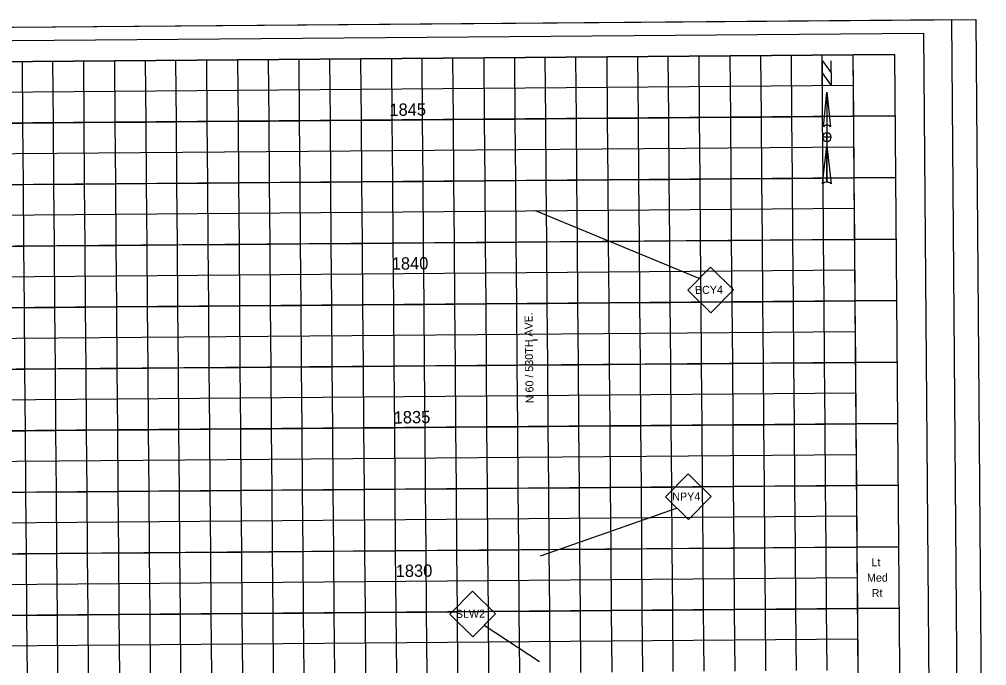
# Model space of a CAD drawing. Extents: x 11670159 to 11702568, y 9558247 to 9571922.
# Drawn here: x 11687520 to 11690664, y 9568756 to 9570857 of the extents above; entities that cross this region are included whole.
import ezdxf

# ---------------------------------------------------------------- set-up
doc = ezdxf.new("R2010")
doc.units = 0
for name, color, linetype in [('dsnAlignmentStation', 7, 'Continuous'), ('dsnNonPlotable', 7, 'Continuous'), ('DsnShtDBGLtRtTextUpper', 7, 'Continuous'), ('DsnShtDBGMedTextUpper', 7, 'Continuous'), ('DsnShtMajorGrid11', 7, 'Continuous'), ('DsnShtMajorGrid12', 7, 'Continuous'), ('DsnShtMajorGrid13', 7, 'Continuous'), ('DsnShtMajorGrid14', 7, 'Continuous'), ('DsnShtMajorGrid15', 7, 'Continuous'), ('DsnShtMajorGrid16', 7, 'Continuous'), ('DsnShtMajorGrid17', 7, 'Continuous'), ('DsnShtMajorGrid18', 7, 'Continuous'), ('DsnShtMajorGrid19', 7, 'Continuous'), ('DsnShtMajorGrid20', 7, 'Continuous'), ('DsnShtMinorGrid11', 7, 'Continuous'), ('DsnShtMinorGrid12', 7, 'Continuous'), ('DsnShtMinorGrid13', 7, 'Continuous'), ('DsnShtMinorGrid14', 7, 'Continuous'), ('DsnShtMinorGrid15', 7, 'Continuous'), ('DsnShtMinorGrid16', 7, 'Continuous'), ('DsnShtMinorGrid17', 7, 'Continuous'), ('DsnShtMinorGrid18', 7, 'Continuous'), ('DsnShtMinorGrid19', 7, 'Continuous'), ('DsnShtMinorGrid20', 7, 'Continuous'), ('DsnShtOutsideBorder', 7, 'Continuous'), ('DsnShtPlotShape', 7, 'Continuous'), ('dsnShtPlotShapeBatchPrint', 7, 'Continuous'), ('dsnTextFinalPlan', 7, 'Continuous'), ('hwyPlanSheetShape', 7, 'Continuous'), ('PvmtMrkngPrplCallout', 7, 'Continuous')]:
    doc.layers.add(name, color=color, linetype=linetype)

msp = doc.modelspace()

# ---------------------------------------------------------------- linework, layer by layer
at = {"layer": 'dsnNonPlotable'}
msp.add_line((11689189, 9569814.8), (11689203.6, 9569815), dxfattribs=at)
msp.add_lwpolyline([(11684229.4, 9570693), (11690229.2, 9570741.4), (11690261.8, 9566701.6), (11684262, 9566653.2)], close=True, dxfattribs=at)
at = {"layer": 'DsnShtMajorGrid11'}
for points in [[(11690378.7, 9568942.6), (11684108.9, 9568892)], [(11687645.4, 9568720.5), (11687643.8, 9568920.5), (11687843.8, 9568922.1), (11687845.4, 9568722.1)], [(11688045.4, 9568723.7), (11688043.8, 9568923.7), (11688243.8, 9568925.3), (11688245.4, 9568725.4)], [(11688445.4, 9568727), (11688443.8, 9568927), (11688643.8, 9568928.6), (11688645.4, 9568728.6)], [(11688845.4, 9568730.2), (11688843.8, 9568930.2), (11689043.7, 9568931.8), (11689045.4, 9568731.8)], [(11689245.4, 9568733.4), (11689243.7, 9568933.4), (11689443.7, 9568935), (11689445.3, 9568735)], [(11689645.3, 9568736.6), (11689643.7, 9568936.6), (11689843.7, 9568938.3), (11689845.3, 9568738.3)], [(11690045.3, 9568739.9), (11690043.7, 9568939.9), (11690243.7, 9568941.5), (11690245.3, 9568741.5)]]:
    msp.add_lwpolyline(points, dxfattribs=at)
at = {"layer": 'DsnShtMajorGrid12'}
for points in [[(11690377.1, 9569142.6), (11684107.3, 9569092)], [(11687443.8, 9568918.9), (11687643.8, 9568920.5), (11687642.2, 9569120.5), (11687842.2, 9569122.1), (11687843.8, 9568922.1), (11688043.8, 9568923.7), (11688042.2, 9569123.7), (11688242.2, 9569125.3), (11688243.8, 9568925.3), (11688443.8, 9568927), (11688442.2, 9569127), (11688642.1, 9569128.6), (11688643.8, 9568928.6), (11688843.8, 9568930.2), (11688842.1, 9569130.2), (11689042.1, 9569131.8), (11689043.7, 9568931.8), (11689243.7, 9568933.4), (11689242.1, 9569133.4), (11689442.1, 9569135), (11689443.7, 9568935), (11689643.7, 9568936.6), (11689642.1, 9569136.6), (11689842.1, 9569138.2), (11689843.7, 9568938.3), (11690043.7, 9568939.9), (11690042.1, 9569139.9), (11690242.1, 9569141.5), (11690243.7, 9568941.5), (11690378.7, 9568942.6), (11684108.9, 9568892)]]:
    msp.add_lwpolyline(points, dxfattribs=at)
at = {"layer": 'DsnShtMajorGrid13'}
for points in [[(11690375.5, 9569342.6), (11684105.7, 9569292)], [(11687442.2, 9569118.9), (11687642.2, 9569120.5), (11687640.6, 9569320.5), (11687840.6, 9569322.1), (11687842.2, 9569122.1), (11688042.2, 9569123.7), (11688040.6, 9569323.7), (11688240.5, 9569325.3), (11688242.2, 9569125.3), (11688442.2, 9569127), (11688440.5, 9569326.9), (11688640.5, 9569328.6), (11688642.1, 9569128.6), (11688842.1, 9569130.2), (11688840.5, 9569330.2), (11689040.5, 9569331.8), (11689042.1, 9569131.8), (11689242.1, 9569133.4), (11689240.5, 9569333.4), (11689440.5, 9569335), (11689442.1, 9569135), (11689642.1, 9569136.6), (11689640.5, 9569336.6), (11689840.5, 9569338.2), (11689842.1, 9569138.2), (11690042.1, 9569139.9), (11690040.5, 9569339.9), (11690240.5, 9569341.5), (11690242.1, 9569141.5), (11690377.1, 9569142.6), (11684107.3, 9569092)]]:
    msp.add_lwpolyline(points, dxfattribs=at)
at = {"layer": 'DsnShtMajorGrid14'}
for points in [[(11690373.9, 9569542.5), (11684104.1, 9569492)], [(11687440.6, 9569318.9), (11687640.6, 9569320.5), (11687639, 9569520.5), (11687838.9, 9569522.1), (11687840.6, 9569322.1), (11688040.6, 9569323.7), (11688038.9, 9569523.7), (11688238.9, 9569525.3), (11688240.5, 9569325.3), (11688440.5, 9569326.9), (11688438.9, 9569526.9), (11688638.9, 9569528.6), (11688640.5, 9569328.6), (11688840.5, 9569330.2), (11688838.9, 9569530.2), (11689038.9, 9569531.8), (11689040.5, 9569331.8), (11689240.5, 9569333.4), (11689238.9, 9569533.4), (11689438.9, 9569535), (11689440.5, 9569335), (11689640.5, 9569336.6), (11689638.9, 9569536.6), (11689838.9, 9569538.2), (11689840.5, 9569338.2), (11690040.5, 9569339.9), (11690038.9, 9569539.8), (11690238.9, 9569541.5), (11690240.5, 9569341.5), (11690375.5, 9569342.6), (11684105.7, 9569292)]]:
    msp.add_lwpolyline(points, dxfattribs=at)
at = {"layer": 'DsnShtMajorGrid15'}
for points in [[(11690372.3, 9569742.5), (11684102.5, 9569692)], [(11687439, 9569518.9), (11687639, 9569520.5), (11687637.3, 9569720.5), (11687837.3, 9569722.1), (11687838.9, 9569522.1), (11688038.9, 9569523.7), (11688037.3, 9569723.7), (11688237.3, 9569725.3), (11688238.9, 9569525.3), (11688438.9, 9569526.9), (11688437.3, 9569726.9), (11688637.3, 9569728.5), (11688638.9, 9569528.6), (11688838.9, 9569530.2), (11688837.3, 9569730.2), (11689037.3, 9569731.8), (11689038.9, 9569531.8), (11689238.9, 9569533.4), (11689237.3, 9569733.4), (11689437.3, 9569735), (11689438.9, 9569535), (11689638.9, 9569536.6), (11689637.3, 9569736.6), (11689837.3, 9569738.2), (11689838.9, 9569538.2), (11690038.9, 9569539.8), (11690037.3, 9569739.8), (11690237.3, 9569741.5), (11690238.9, 9569541.5), (11690373.9, 9569542.5), (11684104.1, 9569492)]]:
    msp.add_lwpolyline(points, dxfattribs=at)
at = {"layer": 'DsnShtMajorGrid16'}
for points in [[(11690370.6, 9569942.5), (11684100.8, 9569892)], [(11687437.3, 9569718.9), (11687637.3, 9569720.5), (11687635.7, 9569920.5), (11687835.7, 9569922.1), (11687837.3, 9569722.1), (11688037.3, 9569723.7), (11688035.7, 9569923.7), (11688235.7, 9569925.3), (11688237.3, 9569725.3), (11688437.3, 9569726.9), (11688435.7, 9569926.9), (11688635.7, 9569928.5), (11688637.3, 9569728.5), (11688837.3, 9569730.2), (11688835.7, 9569930.2), (11689035.7, 9569931.8), (11689037.3, 9569731.8), (11689237.3, 9569733.4), (11689235.7, 9569933.4), (11689435.7, 9569935), (11689437.3, 9569735), (11689637.3, 9569736.6), (11689635.7, 9569936.6), (11689835.7, 9569938.2), (11689837.3, 9569738.2), (11690037.3, 9569739.8), (11690035.7, 9569939.8), (11690235.6, 9569941.4), (11690237.3, 9569741.5), (11690372.3, 9569742.5), (11684102.5, 9569692)]]:
    msp.add_lwpolyline(points, dxfattribs=at)
at = {"layer": 'DsnShtMajorGrid17'}
for points in [[(11690369, 9570142.5), (11684099.2, 9570092)], [(11687435.7, 9569918.9), (11687635.7, 9569920.5), (11687634.1, 9570120.5), (11687834.1, 9570122.1), (11687835.7, 9569922.1), (11688035.7, 9569923.7), (11688034.1, 9570123.7), (11688234.1, 9570125.3), (11688235.7, 9569925.3), (11688435.7, 9569926.9), (11688434.1, 9570126.9), (11688634.1, 9570128.5), (11688635.7, 9569928.5), (11688835.7, 9569930.2), (11688834.1, 9570130.1), (11689034.1, 9570131.8), (11689035.7, 9569931.8), (11689235.7, 9569933.4), (11689234.1, 9570133.4), (11689434.1, 9570135), (11689435.7, 9569935), (11689635.7, 9569936.6), (11689634.1, 9570136.6), (11689834, 9570138.2), (11689835.7, 9569938.2), (11690035.7, 9569939.8), (11690034, 9570139.8), (11690234, 9570141.4), (11690235.6, 9569941.4), (11690370.6, 9569942.5), (11684100.8, 9569892)]]:
    msp.add_lwpolyline(points, dxfattribs=at)
at = {"layer": 'DsnShtMajorGrid18'}
for points in [[(11690367.4, 9570342.5), (11684097.6, 9570291.9)], [(11687434.1, 9570118.9), (11687634.1, 9570120.5), (11687632.5, 9570320.5), (11687832.5, 9570322.1), (11687834.1, 9570122.1), (11688034.1, 9570123.7), (11688032.5, 9570323.7), (11688232.5, 9570325.3), (11688234.1, 9570125.3), (11688434.1, 9570126.9), (11688432.5, 9570326.9), (11688632.5, 9570328.5), (11688634.1, 9570128.5), (11688834.1, 9570130.1), (11688832.5, 9570330.1), (11689032.5, 9570331.8), (11689034.1, 9570131.8), (11689234.1, 9570133.4), (11689232.5, 9570333.4), (11689432.4, 9570335), (11689434.1, 9570135), (11689634.1, 9570136.6), (11689632.4, 9570336.6), (11689832.4, 9570338.2), (11689834, 9570138.2), (11690034, 9570139.8), (11690032.4, 9570339.8), (11690232.4, 9570341.4), (11690234, 9570141.4), (11690369, 9570142.5), (11684099.2, 9570092)]]:
    msp.add_lwpolyline(points, dxfattribs=at)
at = {"layer": 'DsnShtMajorGrid19'}
for points in [[(11690365.8, 9570542.5), (11684096, 9570491.9)], [(11687432.5, 9570318.8), (11687632.5, 9570320.5), (11687630.9, 9570520.5), (11687830.9, 9570522.1), (11687832.5, 9570322.1), (11688032.5, 9570323.7), (11688030.9, 9570523.7), (11688230.9, 9570525.3), (11688232.5, 9570325.3), (11688432.5, 9570326.9), (11688430.9, 9570526.9), (11688630.9, 9570528.5), (11688632.5, 9570328.5), (11688832.5, 9570330.1), (11688830.8, 9570530.1), (11689030.8, 9570531.7), (11689032.5, 9570331.8), (11689232.5, 9570333.4), (11689230.8, 9570533.4), (11689430.8, 9570535), (11689432.4, 9570335), (11689632.4, 9570336.6), (11689630.8, 9570536.6), (11689830.8, 9570538.2), (11689832.4, 9570338.2), (11690032.4, 9570339.8), (11690030.8, 9570539.8), (11690230.8, 9570541.4), (11690232.4, 9570341.4), (11690367.4, 9570342.5), (11684097.6, 9570291.9)]]:
    msp.add_lwpolyline(points, dxfattribs=at)
at = {"layer": 'DsnShtMajorGrid20'}
for points in [[(11690364.2, 9570742.5), (11684094.4, 9570691.9)], [(11687430.9, 9570518.8), (11687630.9, 9570520.5), (11687629.3, 9570720.4), (11687829.3, 9570722.1), (11687830.9, 9570522.1), (11688030.9, 9570523.7), (11688029.3, 9570723.7), (11688229.3, 9570725.3), (11688230.9, 9570525.3), (11688430.9, 9570526.9), (11688429.2, 9570726.9), (11688629.2, 9570728.5), (11688630.9, 9570528.5), (11688830.8, 9570530.1), (11688829.2, 9570730.1), (11689029.2, 9570731.7), (11689030.8, 9570531.7), (11689230.8, 9570533.4), (11689229.2, 9570733.4), (11689429.2, 9570735), (11689430.8, 9570535), (11689630.8, 9570536.6), (11689629.2, 9570736.6), (11689829.2, 9570738.2), (11689830.8, 9570538.2), (11690030.8, 9570539.8), (11690029.2, 9570739.8), (11690229.2, 9570741.4), (11690230.8, 9570541.4), (11690365.8, 9570542.5), (11684096, 9570491.9)]]:
    msp.add_lwpolyline(points, dxfattribs=at)
at = {"layer": 'DsnShtMinorGrid11'}
for points in [[(11687343.8, 9568918.1), (11687543.8, 9568919.7), (11687545.4, 9568719.7)], [(11687745.4, 9568721.3), (11687743.8, 9568921.3), (11687943.8, 9568922.9), (11687945.4, 9568722.9)], [(11688145.4, 9568724.5), (11688143.8, 9568924.5), (11688343.8, 9568926.2), (11688345.4, 9568726.2)], [(11688545.4, 9568727.8), (11688543.8, 9568927.8), (11688743.8, 9568929.4), (11688745.4, 9568729.4)], [(11688945.4, 9568731), (11688943.8, 9568931), (11689143.7, 9568932.6), (11689145.4, 9568732.6)], [(11689345.4, 9568734.2), (11689343.7, 9568934.2), (11689543.7, 9568935.8), (11689545.3, 9568735.8)], [(11689745.3, 9568737.5), (11689743.7, 9568937.4), (11689943.7, 9568939.1), (11689945.3, 9568739.1)], [(11690145.3, 9568740.7), (11690143.7, 9568940.7)], [(11690244.5, 9568841.5), (11684244.7, 9568793.1)]]:
    msp.add_lwpolyline(points, dxfattribs=at)
at = {"layer": 'DsnShtMinorGrid12'}
for points in [[(11687342.2, 9569118.1), (11687542.2, 9569119.7), (11687543.8, 9568919.7), (11687743.8, 9568921.3), (11687742.2, 9569121.3), (11687942.2, 9569122.9), (11687943.8, 9568922.9), (11688143.8, 9568924.5), (11688142.2, 9569124.5), (11688342.2, 9569126.1), (11688343.8, 9568926.2), (11688543.8, 9568927.8), (11688542.2, 9569127.8), (11688742.1, 9569129.4), (11688743.8, 9568929.4), (11688943.8, 9568931), (11688942.1, 9569131), (11689142.1, 9569132.6), (11689143.7, 9568932.6), (11689343.7, 9568934.2), (11689342.1, 9569134.2), (11689542.1, 9569135.8), (11689543.7, 9568935.8), (11689743.7, 9568937.4), (11689742.1, 9569137.4), (11689942.1, 9569139.1), (11689943.7, 9568939.1), (11690143.7, 9568940.7), (11690142.1, 9569140.7)], [(11690242.9, 9569041.5), (11684243.1, 9568993.1)]]:
    msp.add_lwpolyline(points, dxfattribs=at)
at = {"layer": 'DsnShtMinorGrid13'}
for points in [[(11687340.6, 9569318.1), (11687540.6, 9569319.7), (11687542.2, 9569119.7), (11687742.2, 9569121.3), (11687740.6, 9569321.3), (11687940.6, 9569322.9), (11687942.2, 9569122.9), (11688142.2, 9569124.5), (11688140.6, 9569324.5), (11688340.5, 9569326.1), (11688342.2, 9569126.1), (11688542.2, 9569127.8), (11688540.5, 9569327.8), (11688740.5, 9569329.4), (11688742.1, 9569129.4), (11688942.1, 9569131), (11688940.5, 9569331), (11689140.5, 9569332.6), (11689142.1, 9569132.6), (11689342.1, 9569134.2), (11689340.5, 9569334.2), (11689540.5, 9569335.8), (11689542.1, 9569135.8), (11689742.1, 9569137.4), (11689740.5, 9569337.4), (11689940.5, 9569339), (11689942.1, 9569139.1), (11690142.1, 9569140.7), (11690140.5, 9569340.7)], [(11690241.3, 9569241.5), (11684241.5, 9569193.1)]]:
    msp.add_lwpolyline(points, dxfattribs=at)
at = {"layer": 'DsnShtMinorGrid14'}
for points in [[(11687339, 9569518.1), (11687539, 9569519.7), (11687540.6, 9569319.7), (11687740.6, 9569321.3), (11687739, 9569521.3), (11687938.9, 9569522.9), (11687940.6, 9569322.9), (11688140.6, 9569324.5), (11688138.9, 9569524.5), (11688338.9, 9569526.1), (11688340.5, 9569326.1), (11688540.5, 9569327.8), (11688538.9, 9569527.7), (11688738.9, 9569529.4), (11688740.5, 9569329.4), (11688940.5, 9569331), (11688938.9, 9569531), (11689138.9, 9569532.6), (11689140.5, 9569332.6), (11689340.5, 9569334.2), (11689338.9, 9569534.2), (11689538.9, 9569535.8), (11689540.5, 9569335.8), (11689740.5, 9569337.4), (11689738.9, 9569537.4), (11689938.9, 9569539), (11689940.5, 9569339), (11690140.5, 9569340.7), (11690138.9, 9569540.7)], [(11690239.7, 9569441.5), (11684239.9, 9569393.1)]]:
    msp.add_lwpolyline(points, dxfattribs=at)
at = {"layer": 'DsnShtMinorGrid15'}
for points in [[(11687337.4, 9569718.1), (11687537.3, 9569719.7), (11687539, 9569519.7), (11687739, 9569521.3), (11687737.3, 9569721.3), (11687937.3, 9569722.9), (11687938.9, 9569522.9), (11688138.9, 9569524.5), (11688137.3, 9569724.5), (11688337.3, 9569726.1), (11688338.9, 9569526.1), (11688538.9, 9569527.7), (11688537.3, 9569727.7), (11688737.3, 9569729.4), (11688738.9, 9569529.4), (11688938.9, 9569531), (11688937.3, 9569731), (11689137.3, 9569732.6), (11689138.9, 9569532.6), (11689338.9, 9569534.2), (11689337.3, 9569734.2), (11689537.3, 9569735.8), (11689538.9, 9569535.8), (11689738.9, 9569537.4), (11689737.3, 9569737.4), (11689937.3, 9569739), (11689938.9, 9569539), (11690138.9, 9569540.7), (11690137.3, 9569740.6)], [(11690238.1, 9569641.5), (11684238.3, 9569593.1)]]:
    msp.add_lwpolyline(points, dxfattribs=at)
at = {"layer": 'DsnShtMinorGrid16'}
for points in [[(11687335.7, 9569918.1), (11687535.7, 9569919.7), (11687537.3, 9569719.7), (11687737.3, 9569721.3), (11687735.7, 9569921.3), (11687935.7, 9569922.9), (11687937.3, 9569722.9), (11688137.3, 9569724.5), (11688135.7, 9569924.5), (11688335.7, 9569926.1), (11688337.3, 9569726.1), (11688537.3, 9569727.7), (11688535.7, 9569927.7), (11688735.7, 9569929.3), (11688737.3, 9569729.4), (11688937.3, 9569731), (11688935.7, 9569931), (11689135.7, 9569932.6), (11689137.3, 9569732.6), (11689337.3, 9569734.2), (11689335.7, 9569934.2), (11689535.7, 9569935.8), (11689537.3, 9569735.8), (11689737.3, 9569737.4), (11689735.7, 9569937.4), (11689935.7, 9569939), (11689937.3, 9569739), (11690137.3, 9569740.6), (11690135.6, 9569940.6)], [(11690236.5, 9569841.4), (11684236.6, 9569793.1)]]:
    msp.add_lwpolyline(points, dxfattribs=at)
at = {"layer": 'DsnShtMinorGrid17'}
for points in [[(11687334.1, 9570118), (11687534.1, 9570119.7), (11687535.7, 9569919.7), (11687735.7, 9569921.3), (11687734.1, 9570121.3), (11687934.1, 9570122.9), (11687935.7, 9569922.9), (11688135.7, 9569924.5), (11688134.1, 9570124.5), (11688334.1, 9570126.1), (11688335.7, 9569926.1), (11688535.7, 9569927.7), (11688534.1, 9570127.7), (11688734.1, 9570129.3), (11688735.7, 9569929.3), (11688935.7, 9569931), (11688934.1, 9570131), (11689134.1, 9570132.6), (11689135.7, 9569932.6), (11689335.7, 9569934.2), (11689334.1, 9570134.2), (11689534.1, 9570135.8), (11689535.7, 9569935.8), (11689735.7, 9569937.4), (11689734, 9570137.4), (11689934, 9570139), (11689935.7, 9569939), (11690135.6, 9569940.6), (11690134, 9570140.6)], [(11690234.8, 9570041.4), (11684235, 9569993)]]:
    msp.add_lwpolyline(points, dxfattribs=at)
at = {"layer": 'DsnShtMinorGrid18'}
for points in [[(11687332.5, 9570318), (11687532.5, 9570319.7), (11687534.1, 9570119.7), (11687734.1, 9570121.3), (11687732.5, 9570321.3), (11687932.5, 9570322.9), (11687934.1, 9570122.9), (11688134.1, 9570124.5), (11688132.5, 9570324.5), (11688332.5, 9570326.1), (11688334.1, 9570126.1), (11688534.1, 9570127.7), (11688532.5, 9570327.7), (11688732.5, 9570329.3), (11688734.1, 9570129.3), (11688934.1, 9570131), (11688932.5, 9570330.9), (11689132.5, 9570332.6), (11689134.1, 9570132.6), (11689334.1, 9570134.2), (11689332.4, 9570334.2), (11689532.4, 9570335.8), (11689534.1, 9570135.8), (11689734, 9570137.4), (11689732.4, 9570337.4), (11689932.4, 9570339), (11689934, 9570139), (11690134, 9570140.6), (11690132.4, 9570340.6)], [(11690233.2, 9570241.4), (11684233.4, 9570193)]]:
    msp.add_lwpolyline(points, dxfattribs=at)
at = {"layer": 'DsnShtMinorGrid19'}
for points in [[(11687330.9, 9570518), (11687530.9, 9570519.6), (11687532.5, 9570319.7), (11687732.5, 9570321.3), (11687730.9, 9570521.3), (11687930.9, 9570522.9), (11687932.5, 9570322.9), (11688132.5, 9570324.5), (11688130.9, 9570524.5), (11688330.9, 9570526.1), (11688332.5, 9570326.1), (11688532.5, 9570327.7), (11688530.9, 9570527.7), (11688730.9, 9570529.3), (11688732.5, 9570329.3), (11688932.5, 9570330.9), (11688930.8, 9570530.9), (11689130.8, 9570532.6), (11689132.5, 9570332.6), (11689332.4, 9570334.2), (11689330.8, 9570534.2), (11689530.8, 9570535.8), (11689532.4, 9570335.8), (11689732.4, 9570337.4), (11689730.8, 9570537.4), (11689930.8, 9570539), (11689932.4, 9570339), (11690132.4, 9570340.6), (11690130.8, 9570540.6)], [(11690231.6, 9570441.4), (11684231.8, 9570393)]]:
    msp.add_lwpolyline(points, dxfattribs=at)
at = {"layer": 'DsnShtMinorGrid20'}
for points in [[(11687329.3, 9570718), (11687529.3, 9570719.6), (11687530.9, 9570519.6), (11687730.9, 9570521.3), (11687729.3, 9570721.3), (11687929.3, 9570722.9), (11687930.9, 9570522.9), (11688130.9, 9570524.5), (11688129.3, 9570724.5), (11688329.3, 9570726.1), (11688330.9, 9570526.1), (11688530.9, 9570527.7), (11688529.2, 9570727.7), (11688729.2, 9570729.3), (11688730.9, 9570529.3), (11688930.8, 9570530.9), (11688929.2, 9570730.9), (11689129.2, 9570732.5), (11689130.8, 9570532.6), (11689330.8, 9570534.2), (11689329.2, 9570734.2), (11689529.2, 9570735.8), (11689530.8, 9570535.8), (11689730.8, 9570537.4), (11689729.2, 9570737.4), (11689929.2, 9570739), (11689930.8, 9570539), (11690130.8, 9570540.6), (11690129.2, 9570740.6)], [(11690230, 9570641.4), (11684230.2, 9570593)]]:
    msp.add_lwpolyline(points, dxfattribs=at)
at = {"layer": 'DsnShtOutsideBorder'}
msp.add_lwpolyline([(11684094.4, 9570691.9), (11690364.2, 9570742.5), (11690397.4, 9566622.6), (11684127.6, 9566572.1)], close=True, dxfattribs=at)
at = {"layer": 'DsnShtPlotShape'}
msp.add_lwpolyline([(11683828.5, 9570801.8), (11690628.3, 9570856.6), (11690663.8, 9566456.8), (11683864, 9566401.9)], close=True, dxfattribs=at)
at = {"layer": 'dsnShtPlotShapeBatchPrint'}
msp.add_lwpolyline([(11683907.6, 9570802.4), (11690549.2, 9570856), (11690584.6, 9566469.3), (11683943, 9566415.7)], close=True, dxfattribs=at)
at = {"layer": 'dsnTextFinalPlan'}
for p, q in [((11690144.8, 9570620.4), (11690156.1, 9570507.8)), ((11690144.8, 9570620.4), (11690144.8, 9570327.5)), ((11690133.6, 9570507.8), (11690133.6, 9570507.8)), ((11690134, 9570508.8), (11690136.1, 9570511.2)), ((11690144.8, 9570459.9), (11690144.8, 9570459.9)), ((11690130.7, 9570321.9), (11690144.8, 9570445.8))]:
    msp.add_line(p, q, dxfattribs=at)
for points in [[(11690130.7, 9570643), (11690130.8, 9570721.8), (11690158.9, 9570682.4), (11690158.9, 9570721.8)], [(11690133.6, 9570507.8), (11690144.8, 9570620.4), (11690144.8, 9570513.4)], [(11690144.8, 9570459.9), (11690144.8, 9570474), (11690130.7, 9570474)], [(11690158.9, 9570474), (11690144.8, 9570474), (11690144.8, 9570488.1)], [(11690144.8, 9570327.5), (11690144.8, 9570445.8), (11690158.9, 9570321.9)]]:
    msp.add_lwpolyline(points, dxfattribs=at)
msp.add_lwpolyline([(11690158.9, 9570643), (11690130.8, 9570682.4), (11690130.8, 9570721.8), (11690158.9, 9570682.4)], close=True, dxfattribs=at)
for centre, radius, start, end in [((11690144.8, 9570499.3), 14.1, 90.0161, 143.1215), ((11690144.8, 9570499.3), 14.1, 36.8438, 90.0176), ((11690144.8, 9570474), 14.1, 89.9957, 179.9957), ((11690144.8, 9570474), 14.1, 179.9957, 269.9957), ((11690144.8, 9570474), 14.1, 359.9957, 89.9957), ((11690144.8, 9570474), 14.1, 269.9957, 359.9957), ((11690144.8, 9570307.1), 20.4, 89.9851, 133.6147), ((11690144.8, 9570307.1), 20.4, 46.3978, 89.9964)]:
    msp.add_arc(centre, radius, start, end, dxfattribs=at)
at = {"layer": 'hwyPlanSheetShape'}
msp.add_lwpolyline([(11683998.8, 9570760.1), (11690458.6, 9570812.2), (11690493, 9566554), (11684033.2, 9566501.9)], close=True, dxfattribs=at)
at = {"layer": 'PvmtMrkngPrplCallout'}
for p, q in [((11689729.6, 9570013.8), (11689197.7, 9570234.7)), ((11689657.8, 9569267.7), (11689212.4, 9569112.2)), ((11689031.1, 9568887.4), (11689210.8, 9568769.3))]:
    msp.add_line(p, q, dxfattribs=at)
for points in [[(11689692.8, 9569976.4), (11689766.4, 9570051.2), (11689841.3, 9569977.6), (11689767.6, 9569902.8)], [(11689620.4, 9569304.5), (11689694, 9569379.3), (11689768.9, 9569305.7), (11689695.2, 9569230.8)], [(11688919.4, 9568923.6), (11688993.1, 9568998.5), (11689067.9, 9568924.8), (11688994.3, 9568850)]]:
    msp.add_lwpolyline(points, close=True, dxfattribs=at)

# ---------------------------------------------------------------- texts
at = {"layer": 'dsnAlignmentStation'}
for s, rotation, p in [('1845', 0.7991, (11688723.1, 9570542.6)), ('1840', 0.7991, (11688730.7, 9570042.7)), ('1835', 0.7991, (11688737, 9569542.7)), ('1830', 0.6743, (11688743.5, 9569043.8))]:
    msp.add_text(s, height=40, rotation=rotation, dxfattribs=at).set_placement(p)
at = {"layer": 'DsnShtDBGLtRtTextUpper'}
for s, p in [('Lt', (11690289.6, 9569078.9)), ('Rt', (11690290.4, 9568978.9))]:
    msp.add_text(s, height=26, rotation=0.4622, dxfattribs=at).set_placement(p)
at = {"layer": 'DsnShtDBGMedTextUpper'}
msp.add_text('Med', height=26, rotation=0.4622, dxfattribs=at).set_placement((11690275, 9569028.7))
at = {"layer": 'dsnTextFinalPlan'}
msp.add_text('N 60 / 530TH AVE.', height=26, rotation=90.7991, dxfattribs=at).set_placement((11689191.8, 9569609.2))
at = {"layer": 'PvmtMrkngPrplCallout'}
for s, p in [('BCY4', (11689715.9, 9569964.1)), ('NPY4', (11689642.2, 9569292.2)), ('SLW2', (11688939, 9568911.3))]:
    msp.add_text(s, height=26, rotation=0.4622, dxfattribs=at).set_placement(p)

doc.saveas('drawing.dxf')
